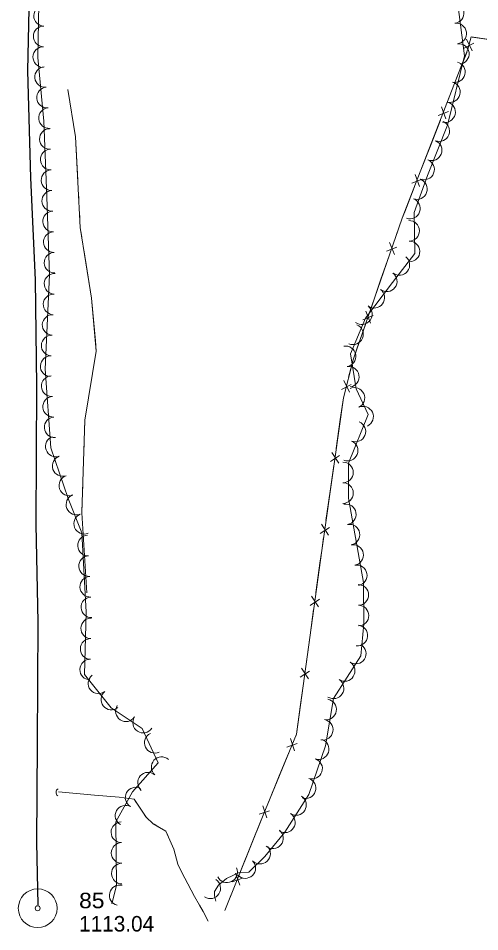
# Model space of a CAD drawing. Extents: x 296677 to 299172, y 46050 to 48373.
# Drawn here: x 297700 to 297878.3, y 46901.4 to 47254.7 of the extents above; entities that cross this region are included whole.
import ezdxf

# ---------------------------------------------------------------- set-up
doc = ezdxf.new("R2010")
doc.units = 0
doc.header["$LTSCALE"] = 2.4
for name, color, linetype, lineweight in [('11', 7, 'Continuous', 25), ('15', 7, 'Continuous', 13), ('18', 7, 'Continuous', 13), ('19', 7, 'Continuous', 13), ('6', 7, 'Continuous', 13)]:
    doc.layers.add(name, color=color, linetype=linetype, lineweight=lineweight)

msp = doc.modelspace()

# ---------------------------------------------------------------- linework, layer by layer
at = {"layer": '11'}
msp.add_lwpolyline([(297707.575, 46911.798), (297707.153, 46935.83), (297707.37, 46974.151), (297707.662, 47021.135), (297706.811, 47058.952), (297707.134, 47112.486), (297706.658, 47153.501), (297704.795, 47192.956), (297703.687, 47234.47), (297704.617, 47282.363), (297704.396, 47323.174), (297704.783, 47360.29), (297706.424, 47397.728)], dxfattribs=at)
at = {"layer": '15'}
for p, q in [((297875.411, 47242.206), (297873.162, 47246.637)), ((297875.366, 47247.459), (297886.661, 47245.844)), ((297872.288, 47243.171), (297876.076, 47245.121)), ((297869.639, 47232.197), (297873.274, 47241.55)), ((297865.506, 47221.563), (297869.639, 47232.197)), ((297862.179, 47217.177), (297866.179, 47218.646)), ((297865.16, 47215.835), (297863.474, 47220.509)), ((297859.468, 47206.028), (297863.103, 47215.38)), ((297855.334, 47195.394), (297859.468, 47206.028)), ((297854.988, 47189.666), (297853.303, 47194.34)), ((297849.296, 47179.859), (297852.931, 47189.211)), ((297852.008, 47191.008), (297856.007, 47192.477)), ((297845.334, 47163.376), (297843.476, 47167.984)), ((297842.306, 47164.607), (297846.248, 47166.223)), ((297840.01, 47153.364), (297843.295, 47162.845)), ((297836.275, 47142.584), (297840.01, 47153.364)), ((297833.114, 47138.078), (297837.056, 47139.694)), ((297836.142, 47136.847), (297834.284, 47141.456)), ((297830.818, 47126.835), (297834.103, 47136.317)), ((297824.861, 47111.135), (297828.655, 47113.074)), ((297827.981, 47110.161), (297825.746, 47114.598)), ((297822.824, 47088.264), (297824.418, 47099.561)), ((297823.795, 47082.609), (297821.087, 47086.774)), ((297820.587, 47083.234), (297824.145, 47085.578)), ((297820.481, 47071.762), (297821.895, 47081.696)), ((297818.874, 47060.467), (297820.481, 47071.762)), ((297819.84, 47054.81), (297817.136, 47058.979)), ((297816.632, 47055.44), (297820.193, 47057.779)), ((297814.998, 47032.659), (297816.55, 47043.962)), ((297815.991, 47027.008), (297813.267, 47031.163)), ((297812.78, 47027.621), (297816.33, 47029.978)), ((297812.73, 47016.147), (297814.096, 47026.088)), ((297811.178, 47004.844), (297812.73, 47016.147)), ((297808.96, 46999.806), (297812.51, 47002.163)), ((297812.171, 46999.192), (297809.447, 47003.348)), ((297808.911, 46988.332), (297810.276, 46998.273)), ((297803.766, 46972.759), (297807.793, 46974.147)), ((297806.719, 46971.358), (297805.127, 46976.064)), ((297800.832, 46961.666), (297804.653, 46970.944)), ((297796.487, 46951.116), (297800.832, 46961.666)), ((297796.027, 46945.397), (297794.435, 46950.103)), ((297793.074, 46946.798), (297797.102, 46948.187)), ((297790.237, 46935.666), (297793.974, 46944.978)), ((297785.987, 46925.078), (297790.237, 46935.666)), ((297782.612, 46920.729), (297786.627, 46922.154)), ((297785.578, 46919.354), (297783.944, 46924.046)), ((297779.778, 46909.61), (297783.516, 46918.922))]:
    msp.add_line(p, q, dxfattribs=at)
for points in [[(297779.778, 46909.61), (297794.554, 46946.422), (297807.458, 46977.755), (297817.225, 47048.875), (297822.114, 47083.236), (297825.595, 47107.902), (297829.355, 47122.614), (297848.322, 47177.352), (297873.74, 47242.748), (297874.944, 47247.519), (297893.603, 47244.852), (297946.629, 47240.386), (297992.624, 47236.365), (298024.19, 47232.996), (298029.924, 47242.469), (298041.045, 47272.217)], [(297845.467, 47169.113), (297848.322, 47177.352), (297849.296, 47179.859)], [(297827.636, 47115.889), (297829.355, 47122.614), (297830.818, 47126.835)], [(297824.418, 47099.561), (297825.595, 47107.902), (297825.994, 47109.462)], [(297816.55, 47043.962), (297817.225, 47048.875), (297817.94, 47053.9)], [(297807.179, 46977.077), (297807.458, 46977.755), (297808.911, 46988.332)]]:
    msp.add_lwpolyline(points, dxfattribs=at)
msp.add_arc((297716.281, 46955.263), 1.721, 124.11055, 230.35012, dxfattribs=at)
at = {"layer": '18'}
for points in [[(297708.075, 47267.349), (297707.521, 47239.557), (297709.852, 47214.968), (297710.948, 47185.7), (297712.066, 47155.451), (297710.33, 47119.058), (297712.472, 47088.542), (297719.226, 47068.996), (297724.578, 47055.737), (297726.194, 47024.963), (297725.607, 47000.836), (297735.839, 46987.923), (297747.868, 46980), (297754.013, 46966.665), (297744.13, 46955.45), (297737.684, 46943.877), (297737.953, 46919.217), (297736.11, 46912.121)], [(297776.292, 46913.156), (297775.783, 46915.298), (297775.795, 46916.912), (297777.391, 46919.401), (297780.457, 46921.95), (297785.049, 46924.14), (297789.088, 46924.472), (297795.211, 46930.428), (297803.004, 46939.868), (297812.301, 46954.394), (297818.682, 46973.279), (297821.754, 46991.616), (297832.303, 47008.085), (297833.554, 47020.435), (297833.381, 47036.43), (297827.527, 47069.14), (297827.517, 47082.59), (297835.122, 47101.446), (297830.515, 47111.39), (297828.392, 47124.874), (297834.163, 47138.713), (297844.574, 47152.496), (297853.237, 47163.679), (297852.955, 47179.551), (297858.094, 47193.908), (297865.803, 47213.378), (297872.393, 47240.229), (297869.341, 47264.273)]]:
    msp.add_lwpolyline(points, dxfattribs=at)
for centre, start, end in [((297868.188, 47256.769), 277.24176, 97.22643), ((297709.932, 47255.694), 88.86569, 268.85037), ((297869.193, 47248.852), 277.24176, 97.22643), ((297709.773, 47247.714), 88.86569, 268.85037), ((297709.614, 47239.735), 88.86569, 268.85037), ((297870.198, 47240.934), 277.24176, 97.22643), ((297710.333, 47232.027), 95.42303, 275.40771), ((297868.695, 47233.923), 256.2182, 76.20288), ((297711.086, 47224.081), 95.42303, 275.40771), ((297866.792, 47226.172), 256.2182, 76.20288), ((297864.89, 47218.421), 256.2182, 76.20288), ((297711.84, 47216.136), 95.42303, 275.40771), ((297862.646, 47211.078), 248.40694, 68.39162), ((297712.202, 47208.045), 92.15222, 272.13689), ((297859.707, 47203.657), 248.40694, 68.39162), ((297712.5, 47200.069), 92.15222, 272.13689), ((297856.769, 47196.236), 248.40694, 68.39162), ((297712.799, 47192.094), 92.15222, 272.13689), ((297854.003, 47188.677), 250.31314, 70.29782), ((297713.097, 47184.117), 92.12434, 272.10902), ((297851.313, 47181.162), 250.31314, 70.29782), ((297713.392, 47176.141), 92.12434, 272.10902), ((297850.991, 47172.498), 271.02554, 91.01021), ((297713.686, 47168.165), 92.12434, 272.10902), ((297851.133, 47164.518), 271.02554, 91.01021), ((297713.981, 47160.19), 92.12434, 272.10902), ((297847.234, 47159.341), 232.24422, 52.2289), ((297713.994, 47152.039), 87.27664, 267.26132), ((297842.34, 47153.005), 232.94206, 52.92674), ((297713.614, 47144.067), 87.27664, 267.26132), ((297837.53, 47146.636), 232.94206, 52.92674), ((297832.719, 47140.267), 232.94206, 52.92674), ((297713.234, 47136.094), 87.27664, 267.26132), ((297829.306, 47132.492), 247.37104, 67.35572), ((297712.854, 47128.122), 87.27664, 267.26132), ((297826.422, 47123.958), 278.95519, 98.93987), ((297712.473, 47120.15), 87.27664, 267.26132), ((297827.663, 47116.074), 278.95519, 98.93987), ((297712.889, 47112.433), 94.02282, 274.0075), ((297829.843, 47107.871), 294.86569, 114.85037), ((297713.448, 47104.471), 94.02282, 274.0075), ((297833.198, 47100.629), 294.86569, 114.85037), ((297714.007, 47096.51), 94.02282, 274.0075), ((297830.225, 47094.888), 248.04246, 68.02714), ((297714.492, 47089.091), 109.06994, 289.05461), ((297827.239, 47087.487), 248.04246, 68.02714), ((297717.099, 47081.548), 109.06994, 289.05461), ((297825.431, 47079.045), 270.05026, 90.03494), ((297719.705, 47074.004), 109.06994, 289.05461), ((297825.437, 47071.063), 270.05026, 90.03494), ((297722.437, 47066.621), 111.98914, 291.97382), ((297826.538, 47062.81), 280.15428, 100.13896), ((297725.425, 47059.22), 111.98914, 291.97382), ((297827.944, 47054.954), 280.15428, 100.13896), ((297726.93, 47050.785), 93.01361, 272.99829), ((297829.35, 47047.098), 280.15428, 100.13896), ((297727.348, 47042.815), 93.01361, 272.99829), ((297830.756, 47039.241), 280.15428, 100.13896), ((297727.767, 47034.845), 93.01361, 272.99829), ((297831.344, 47031.656), 270.62734, 90.61202), ((297728.185, 47026.875), 93.01361, 272.99829), ((297831.43, 47023.676), 270.62734, 90.61202), ((297728.132, 47018.738), 88.61395, 268.59863), ((297831, 47015.952), 264.22358, 84.20826), ((297727.938, 47010.759), 88.61395, 268.59863), ((297830.39, 47008.971), 237.36661, 57.35128), ((297727.744, 47002.78), 88.61395, 268.59863), ((297826.085, 47002.25), 237.36661, 57.35128), ((297730.962, 46997.442), 128.40026, 308.38493), ((297821.78, 46995.53), 237.36661, 57.35128), ((297735.918, 46991.186), 128.40026, 308.38493), ((297818.922, 46987.354), 260.49721, 80.48189), ((297741.558, 46986.657), 146.63643, 326.62111), ((297748.224, 46982.267), 146.63643, 326.62111), ((297817.603, 46979.482), 260.49721, 80.48189), ((297752.708, 46974.488), 114.74873, 294.73341), ((297816.05, 46972.014), 251.33821, 71.32289), ((297755.362, 46965.037), 48.62018, 228.60485), ((297813.495, 46964.453), 251.33821, 71.32289), ((297750.085, 46959.049), 48.62018, 228.60485), ((297810.94, 46956.891), 251.33821, 71.32289), ((297745.301, 46953.259), 60.89046, 240.87514), ((297807.28, 46950.424), 237.38741, 57.37209), ((297741.417, 46946.287), 60.89046, 240.87514), ((297802.977, 46943.701), 237.38741, 57.37209), ((297739.817, 46939.841), 90.63264, 270.61732), ((297798.358, 46937.522), 230.46698, 50.45166), ((297739.904, 46931.86), 90.63264, 270.61732), ((297793.391, 46931.572), 224.21556, 44.20024), ((297739.991, 46923.879), 90.63264, 270.61732), ((297787.67, 46926.007), 224.21556, 44.20024), ((297780.652, 46924.357), 205.5049, 25.48958), ((297774.131, 46918.187), 237.3388, 57.32348), ((297739.135, 46915.458), 75.44827, 255.43295)]:
    msp.add_arc(centre, 3.991, start, end, dxfattribs=at)
at = {"layer": '19'}
for p, q in [((297723.356, 47184.633), (297723.226, 47187.08)), ((297723.746, 47177.295), (297723.616, 47179.741)), ((297724.526, 47169.999), (297724.148, 47172.418)), ((297725.337, 47087.545), (297725.418, 47089.992)), ((297725.092, 47080.205), (297725.174, 47082.652)), ((297724.847, 47072.865), (297724.929, 47075.311)), ((297748.106, 46947.632), (297749.306, 46945.852)), ((297752.422, 46942.927), (297754.267, 46941.85)), ((297757.456, 46939.244), (297758.317, 46937.281))]:
    msp.add_line(p, q, dxfattribs=at)
for points in [[(297726.505, 47032.53), (297724.534, 47063.474), (297725.727, 47099.249), (297730.117, 47125.933), (297728.207, 47146.451), (297723.931, 47173.805), (297722.07, 47208.831), (297719.109, 47227.208)], [(297722.966, 47191.972), (297722.07, 47208.831), (297719.109, 47227.208)], [(297729.74, 47129.98), (297728.207, 47146.451), (297725.282, 47165.161)], [(297725.582, 47094.886), (297725.727, 47099.249), (297730.117, 47125.933), (297729.74, 47129.98)], [(297726.505, 47032.53), (297724.534, 47063.474), (297724.684, 47067.971)], [(297715.494, 46955.513), (297729.418, 46954.244), (297738.931, 46953.378), (297744.708, 46952.673), (297749.403, 46945.708), (297752.088, 46943.122), (297757.017, 46940.245), (297760.068, 46933.291), (297761.623, 46927.449), (297763.113, 46924.347), (297765.527, 46919.844), (297768.09, 46915.022), (297770.015, 46911.675), (297771.387, 46909.249), (297773.352, 46905.489)], [(297715.494, 46955.513), (297729.418, 46954.244), (297738.931, 46953.378), (297744.708, 46952.673), (297745.706, 46951.193)], [(297760.04, 46933.355), (297760.068, 46933.291), (297761.623, 46927.449), (297763.113, 46924.347), (297765.527, 46919.844), (297768.09, 46915.022), (297770.015, 46911.675), (297771.387, 46909.249), (297773.352, 46905.489)]]:
    msp.add_lwpolyline(points, dxfattribs=at)
at = {"layer": '6'}
for radius in [7.5, 0.96]:
    msp.add_circle((297707.454, 46910.456), radius, dxfattribs=at)

# ---------------------------------------------------------------- texts
at = {"layer": '6', "width": 1.1}
msp.add_text('85', height=6, dxfattribs=at).set_placement((297723.454, 46910.456))
at = {"layer": '6'}
msp.add_text('1113.04', height=6, dxfattribs=at).set_placement((297723.454, 46901.456))

doc.saveas('drawing.dxf')
